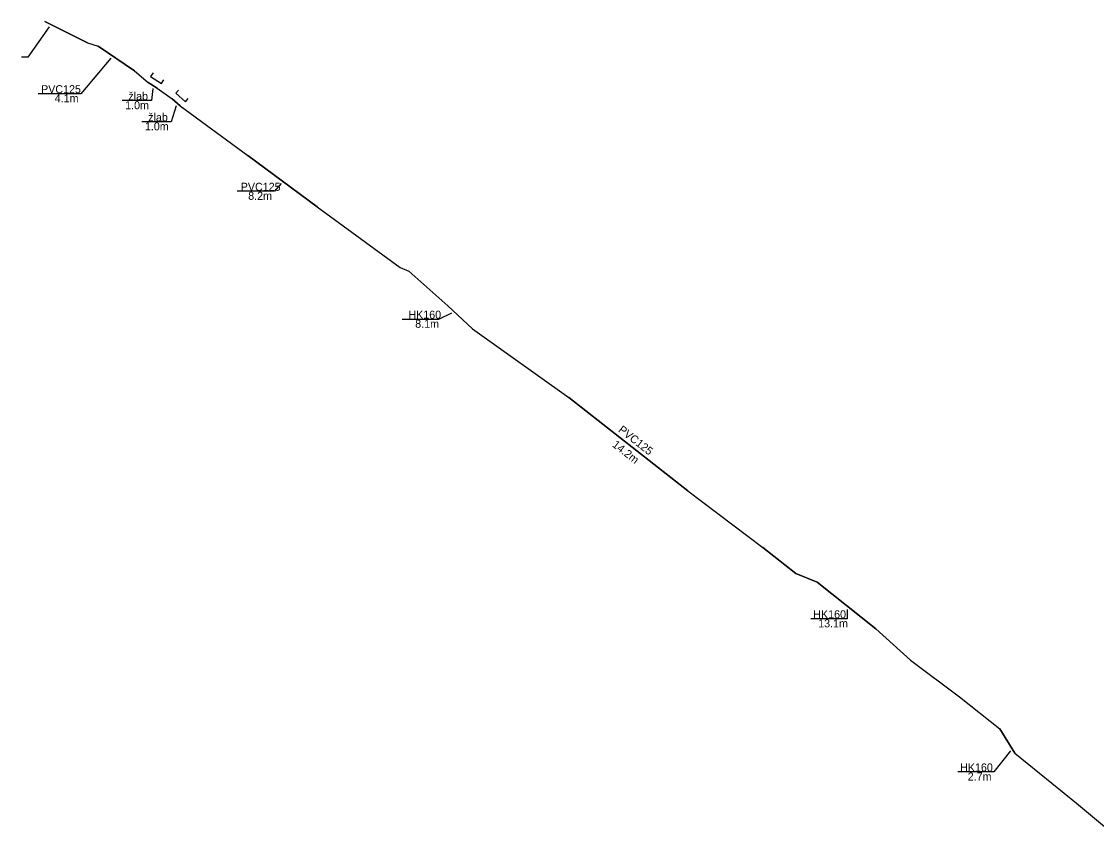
# Model space of a CAD drawing. Extents: x -594469 to -594054, y -1167536 to -1167142.
# Drawn here: x -594469.4 to -594368.7, y -1167219 to -1167141.7 of the extents above; entities that cross this region are included whole.
import ezdxf

# ---------------------------------------------------------------- set-up
doc = ezdxf.new("R2010")
doc.units = 0
for name, color, linetype in [('Vrstva 1', 7, 'Continuous'), ('Vrstva 5', 7, 'Continuous'), ('Vrstva 6', 7, 'Continuous'), ('Vrstva 60', 7, 'Continuous')]:
    doc.layers.add(name, color=color, linetype=linetype)

msp = doc.modelspace()

# ---------------------------------------------------------------- linework, layer by layer
at = {"layer": 'Vrstva 1'}
msp.add_lwpolyline([(-594467.22, -1167141.74), (-594463.23, -1167143.72), (-594462.22, -1167144.05), (-594458.82, -1167146.35), (-594457.53, -1167147.45), (-594456.69, -1167147.98), (-594455.28, -1167148.97), (-594454.52, -1167149.64), (-594448.19, -1167154.28), (-594441.7, -1167159.09), (-594433.92, -1167164.77), (-594433.12, -1167165.13), (-594429.46, -1167168.38), (-594427.13, -1167170.53), (-594418.12, -1167176.95), (-594406.95, -1167185.7), (-594399.94, -1167191.01), (-594396.84, -1167193.44), (-594394.83, -1167194.25), (-594389.36, -1167198.63), (-594386.11, -1167201.55), (-594381.5, -1167204.97), (-594377.72, -1167207.99), (-594376.31, -1167210.26), (-594370.54, -1167214.93), (-594365.67, -1167219)], dxfattribs=at)
at = {"layer": 'Vrstva 5'}
for points in [[(-594463.23, -1167143.72), (-594467.22, -1167141.74)], [(-594458.82, -1167146.35), (-594462.22, -1167144.05)], [(-594457.08, -1167146.55), (-594457.3, -1167146.89), (-594456.28, -1167147.53), (-594456.07, -1167147.19)], [(-594456.69, -1167147.98), (-594457.53, -1167147.45)], [(-594454.69, -1167148.16), (-594454.95, -1167148.46), (-594454.05, -1167149.25), (-594453.79, -1167148.95)], [(-594454.52, -1167149.64), (-594455.28, -1167148.97)], [(-594441.7, -1167159.09), (-594448.19, -1167154.28)], [(-594427.13, -1167170.53), (-594429.46, -1167168.38), (-594433.12, -1167165.13)], [(-594406.95, -1167185.7), (-594418.12, -1167176.95)], [(-594389.36, -1167198.63), (-594394.83, -1167194.25), (-594396.84, -1167193.44), (-594399.94, -1167191.01)], [(-594376.31, -1167210.26), (-594377.72, -1167207.99)]]:
    msp.add_lwpolyline(points, dxfattribs=at)
at = {"layer": 'Vrstva 60'}
for p, q in [((-594466.8, -1167142.23), (-594468.81, -1167145.09)), ((-594468.81, -1167145.09), (-594469.4, -1167145.09)), ((-594461.03, -1167145.16), (-594463.83, -1167148.5)), ((-594457.11, -1167148.01), (-594457.23, -1167149.15)), ((-594463.83, -1167148.5), (-594467.83, -1167148.5)), ((-594457.23, -1167149.15), (-594459.98, -1167149.15)), ((-594454.91, -1167149.63), (-594455.38, -1167151.13)), ((-594455.38, -1167151.13), (-594458.13, -1167151.13)), ((-594445.08, -1167156.9), (-594445.7, -1167157.64)), ((-594445.7, -1167157.64), (-594449.2, -1167157.64)), ((-594429.11, -1167169.04), (-594430.34, -1167169.65)), ((-594430.34, -1167169.65), (-594433.74, -1167169.65)), ((-594392.04, -1167197.68), (-594395.44, -1167197.68)), ((-594392.03, -1167196.81), (-594392.04, -1167197.68)), ((-594376.74, -1167210.04), (-594378.28, -1167212.02)), ((-594378.28, -1167212.02), (-594381.68, -1167212.02))]:
    msp.add_line(p, q, dxfattribs=at)

# ---------------------------------------------------------------- texts
at = {"layer": 'Vrstva 6'}
for s, p in [('PVC125', (-594467.57, -1167148.45)), ('žlab', (-594459.39, -1167149.1)), ('4.1m', (-594466.29, -1167149.3)), ('1.0m', (-594459.69, -1167149.95)), ('žlab', (-594457.53, -1167151.08)), ('1.0m', (-594457.84, -1167151.93)), ('PVC125', (-594448.86, -1167157.59)), ('8.2m', (-594448.16, -1167158.44)), ('HK160', (-594433.15, -1167169.57)), ('8.1m', (-594432.51, -1167170.42)), ('HK160', (-594395.21, -1167197.63)), ('13.1m', (-594394.75, -1167198.48)), ('HK160', (-594381.45, -1167211.97)), ('2.7m', (-594380.74, -1167212.82))]:
    msp.add_text(s, height=0.75, dxfattribs=at).set_placement(p)
for s, p in [('PVC125', (-594413.54, -1167180.1)), ('14.2m', (-594414.11, -1167181.49))]:
    msp.add_text(s, height=0.75, rotation=321.9267, dxfattribs=at).set_placement(p)

doc.saveas('drawing.dxf')
